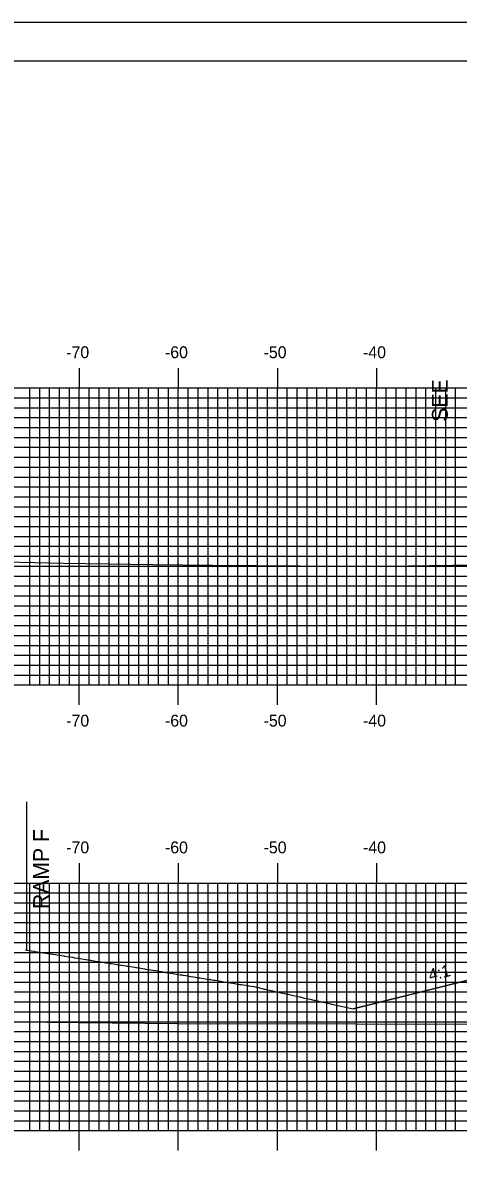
# Model space of a CAD drawing. Extents: x 854116 to 854460, y 364366 to 364586.
# Drawn here: x 854206.5 to 854250.5, y 364471.3 to 364585.7 of the extents above; entities that cross this region are included whole.
import ezdxf

# ---------------------------------------------------------------- set-up
doc = ezdxf.new("R2010")
doc.units = 0
for name, color, linetype in [('ANNOTATION', 7, 'Continuous'), ('BORDER', 7, 'Continuous'), ('D_Roadway_Centerline', 7, 'Continuous'), ('D_Roadway_SlopeLines', 7, 'Continuous'), ('D_Roadway_SubGrade', 7, 'Continuous'), ('H_V ANNOTATION', 7, 'Continuous'), ('MAJOR', 7, 'Continuous'), ('MINOR', 7, 'Continuous'), ('PLOT BOUNDARY', 7, 'Continuous'), ('S_Roadway_Centerline', 7, 'Continuous')]:
    doc.layers.add(name, color=color, linetype=linetype)

msp = doc.modelspace()

# ---------------------------------------------------------------- linework, layer by layer
at = {"layer": 'BORDER'}
msp.add_lwpolyline([(854132.63, 364371.79), (854452.63, 364371.79), (854452.63, 364581.79), (854132.63, 364581.79)], close=True, dxfattribs=at)
at = {"layer": 'D_Roadway_Centerline'}
for points in [[(854206.79, 364492.04), (854206.89, 364492.03), (854206.89, 364492.03), (854206.91, 364492.02), (854207.66, 364491.9), (854207.74, 364491.89), (854207.75, 364491.89), (854207.98, 364491.85), (854208.01, 364491.85), (854208.37, 364491.79), (854208.43, 364491.78), (854209.04, 364491.69), (854209.19, 364491.66), (854209.19, 364491.66), (854209.2, 364491.66), (854209.37, 364491.63), (854209.98, 364491.54), (854210.43, 364491.47), (854210.63, 364491.43), (854210.67, 364491.43), (854210.75, 364491.41), (854211.24, 364491.34), (854211.53, 364491.29), (854211.76, 364491.25), (854212.08, 364491.2), (854212.18, 364491.19), (854212.31, 364491.17), (854212.7, 364491.1), (854213.09, 364491.04), (854213.22, 364491.02), (854213.36, 364491), (854213.46, 364490.98), (854213.54, 364490.97), (854213.68, 364490.95), (854213.88, 364490.91), (854214.18, 364490.87), (854214.67, 364490.79), (854214.89, 364490.75), (854215, 364490.74), (854215.32, 364490.68), (854215.46, 364490.66), (854215.67, 364490.63), (854216.25, 364490.54), (854216.43, 364490.51), (854216.48, 364490.5), (854216.95, 364490.42), (854217.04, 364490.41), (854217.16, 364490.39), (854217.84, 364490.28), (854217.95, 364490.26), (854217.96, 364490.26), (854218.01, 364490.25), (854218.64, 364490.15), (854218.82, 364490.12), (854218.82, 364490.12), (854218.82, 364490.12), (854218.92, 364490.1), (854219.41, 364490.03), (854219.44, 364490.02), (854219.45, 364490.02), (854219.45, 364490.02), (854220.15, 364489.91), (854220.25, 364489.89), (854220.34, 364489.88), (854220.95, 364489.78), (854220.97, 364489.77), (854221.05, 364489.76), (854221.66, 364489.66), (854221.86, 364489.63), (854222.03, 364489.6), (854222.46, 364489.53), (854222.6, 364489.51), (854222.67, 364489.5), (854222.98, 364489.45), (854223.49, 364489.37), (854223.76, 364489.32), (854223.97, 364489.29), (854224.13, 364489.26), (854224.3, 364489.23), (854224.35, 364489.23), (854224.39, 364489.22), (854224.79, 364489.16), (854225.12, 364489.1), (854225.34, 364489.06), (854225.5, 364489.04), (854225.78, 364488.99), (854225.94, 364488.97), (854226.52, 364488.87), (854226.77, 364488.83), (854226.84, 364488.82), (854227.03, 364488.79), (854227.47, 364488.72), (854227.6, 364488.7), (854227.75, 364488.67), (854228.43, 364488.56), (854228.44, 364488.56), (854228.57, 364488.54), (854229.22, 364488.43), (854229.26, 364488.43), (854229.3, 364488.42), (854229.86, 364488.33), (854230.09, 364488.28), (854230.09, 364488.28), (854230.09, 364488.28), (854230.09, 364488.28), (854230.13, 364488.27), (854230.14, 364488.26), (854230.93, 364488.09), (854231, 364488.07), (854231.69, 364487.92), (854231.7, 364487.92), (854231.77, 364487.9), (854231.91, 364487.87), (854232.61, 364487.71), (854232.77, 364487.68), (854233.26, 364487.57), (854233.31, 364487.56), (854233.46, 364487.52), (854233.73, 364487.46), (854234.31, 364487.33), (854234.52, 364487.29), (854234.84, 364487.21), (854234.98, 364487.18), (854235.16, 364487.14), (854235.53, 364487.06), (854235.9, 364486.97), (854235.96, 364486.96), (854236.01, 364486.95), (854236.25, 364486.9), (854236.43, 364486.86), (854236.7, 364486.8), (854236.87, 364486.76), (854237.48, 364486.62), (854237.73, 364486.56), (854239.89, 364486.08)], [(854239.89, 364486.08), (854253.36, 364489.44), (854264.23, 364492.16), (854268.23, 364492.24), (854282.23, 364491.4), (854290.23, 364490.92), (854302.23, 364487.92), (854303.39, 364487.63), (854318.77, 364483.79)]]:
    msp.add_lwpolyline(points, dxfattribs=at)
at = {"layer": 'D_Roadway_SlopeLines'}
msp.add_lwpolyline([(854264.23, 364492.16), (854239.89, 364486.08)], dxfattribs=at)
at = {"layer": 'D_Roadway_SubGrade'}
msp.add_line((854206.91, 364506.98), (854206.91, 364492.02), dxfattribs=at)
at = {"layer": 'MAJOR'}
for p, q in [((854212.23, 364550.79), (854212.23, 364548.79)), ((854222.23, 364550.79), (854222.23, 364548.79)), ((854232.23, 364550.79), (854232.23, 364548.79)), ((854242.23, 364550.79), (854242.23, 364548.79)), ((854142.23, 364548.79), (854422.23, 364548.79)), ((854142.23, 364548.79), (854422.23, 364548.79)), ((854212.23, 364518.79), (854212.23, 364548.79)), ((854222.23, 364518.79), (854222.23, 364548.79)), ((854232.23, 364518.79), (854232.23, 364548.79)), ((854242.23, 364518.79), (854242.23, 364548.79)), ((854142.23, 364543.79), (854422.23, 364543.79)), ((854142.23, 364538.79), (854422.23, 364538.79)), ((854142.23, 364533.79), (854422.23, 364533.79)), ((854142.23, 364528.79), (854422.23, 364528.79)), ((854142.23, 364523.79), (854422.23, 364523.79)), ((854142.23, 364518.79), (854422.23, 364518.79)), ((854142.23, 364518.79), (854422.23, 364518.79)), ((854212.23, 364516.78), (854212.23, 364518.79)), ((854222.23, 364516.78), (854222.23, 364518.79)), ((854232.23, 364516.78), (854232.23, 364518.79)), ((854242.23, 364516.78), (854242.23, 364518.79)), ((854212.23, 364500.79), (854212.23, 364498.79)), ((854222.23, 364500.79), (854222.23, 364498.79)), ((854232.23, 364500.79), (854232.23, 364498.79)), ((854242.23, 364500.79), (854242.23, 364498.79)), ((854142.23, 364498.79), (854422.23, 364498.79)), ((854142.23, 364498.79), (854422.23, 364498.79)), ((854212.23, 364473.79), (854212.23, 364498.79)), ((854222.23, 364473.79), (854222.23, 364498.79)), ((854232.23, 364473.79), (854232.23, 364498.79)), ((854242.23, 364473.79), (854242.23, 364498.79)), ((854142.23, 364493.79), (854422.23, 364493.79)), ((854142.23, 364488.79), (854422.23, 364488.79)), ((854142.23, 364483.79), (854422.23, 364483.79)), ((854142.23, 364478.79), (854422.23, 364478.79)), ((854142.23, 364473.79), (854422.23, 364473.79)), ((854142.23, 364473.79), (854422.23, 364473.79)), ((854212.23, 364471.78), (854212.23, 364473.79)), ((854222.23, 364471.78), (854222.23, 364473.79)), ((854232.23, 364471.78), (854232.23, 364473.79)), ((854242.23, 364471.78), (854242.23, 364473.79))]:
    msp.add_line(p, q, dxfattribs=at)
at = {"layer": 'MINOR'}
for p, q in [((854207.23, 364518.79), (854207.23, 364548.79)), ((854208.23, 364518.79), (854208.23, 364548.79)), ((854209.23, 364518.79), (854209.23, 364548.79)), ((854210.23, 364518.79), (854210.23, 364548.79)), ((854211.23, 364518.79), (854211.23, 364548.79)), ((854213.23, 364518.79), (854213.23, 364548.79)), ((854214.23, 364518.79), (854214.23, 364548.79)), ((854215.23, 364518.79), (854215.23, 364548.79)), ((854216.23, 364518.79), (854216.23, 364548.79)), ((854217.23, 364518.79), (854217.23, 364548.79)), ((854218.23, 364518.79), (854218.23, 364548.79)), ((854219.23, 364518.79), (854219.23, 364548.79)), ((854220.23, 364518.79), (854220.23, 364548.79)), ((854221.23, 364518.79), (854221.23, 364548.79)), ((854223.23, 364518.79), (854223.23, 364548.79)), ((854224.23, 364518.79), (854224.23, 364548.79)), ((854225.23, 364518.79), (854225.23, 364548.79)), ((854226.23, 364518.79), (854226.23, 364548.79)), ((854227.23, 364518.79), (854227.23, 364548.79)), ((854228.23, 364518.79), (854228.23, 364548.79)), ((854229.23, 364518.79), (854229.23, 364548.79)), ((854230.23, 364518.79), (854230.23, 364548.79)), ((854231.23, 364518.79), (854231.23, 364548.79)), ((854233.23, 364518.79), (854233.23, 364548.79)), ((854234.23, 364518.79), (854234.23, 364548.79)), ((854235.23, 364518.79), (854235.23, 364548.79)), ((854236.23, 364518.79), (854236.23, 364548.79)), ((854237.23, 364518.79), (854237.23, 364548.79)), ((854238.23, 364518.79), (854238.23, 364548.79)), ((854239.23, 364518.79), (854239.23, 364548.79)), ((854240.23, 364518.79), (854240.23, 364548.79)), ((854241.23, 364518.79), (854241.23, 364548.79)), ((854243.23, 364518.79), (854243.23, 364548.79)), ((854244.23, 364518.79), (854244.23, 364548.79)), ((854245.23, 364518.79), (854245.23, 364548.79)), ((854246.23, 364518.79), (854246.23, 364548.79)), ((854247.23, 364518.79), (854247.23, 364548.79)), ((854248.23, 364518.79), (854248.23, 364548.79)), ((854249.23, 364518.79), (854249.23, 364548.79)), ((854250.23, 364518.79), (854250.23, 364548.79)), ((854142.23, 364547.79), (854422.23, 364547.79)), ((854142.23, 364546.79), (854422.23, 364546.79)), ((854142.23, 364545.79), (854422.23, 364545.79)), ((854142.23, 364544.79), (854422.23, 364544.79)), ((854142.23, 364542.79), (854422.23, 364542.79)), ((854142.23, 364541.79), (854422.23, 364541.79)), ((854142.23, 364540.79), (854422.23, 364540.79)), ((854142.23, 364539.79), (854422.23, 364539.79)), ((854142.23, 364537.79), (854422.23, 364537.79)), ((854142.23, 364536.79), (854422.23, 364536.79)), ((854142.23, 364535.79), (854422.23, 364535.79)), ((854142.23, 364534.79), (854422.23, 364534.79)), ((854142.23, 364532.79), (854422.23, 364532.79)), ((854142.23, 364531.79), (854422.23, 364531.79)), ((854142.23, 364530.79), (854422.23, 364530.79)), ((854142.23, 364529.79), (854422.23, 364529.79)), ((854142.23, 364527.79), (854422.23, 364527.79)), ((854142.23, 364526.79), (854422.23, 364526.79)), ((854142.23, 364525.79), (854422.23, 364525.79)), ((854142.23, 364524.79), (854422.23, 364524.79)), ((854142.23, 364522.79), (854422.23, 364522.79)), ((854142.23, 364521.79), (854422.23, 364521.79)), ((854142.23, 364520.79), (854422.23, 364520.79)), ((854142.23, 364519.79), (854422.23, 364519.79)), ((854207.23, 364473.79), (854207.23, 364498.79)), ((854208.23, 364473.79), (854208.23, 364498.79)), ((854209.23, 364473.79), (854209.23, 364498.79)), ((854210.23, 364473.79), (854210.23, 364498.79)), ((854211.23, 364473.79), (854211.23, 364498.79)), ((854213.23, 364473.79), (854213.23, 364498.79)), ((854214.23, 364473.79), (854214.23, 364498.79)), ((854215.23, 364473.79), (854215.23, 364498.79)), ((854216.23, 364473.79), (854216.23, 364498.79)), ((854217.23, 364473.79), (854217.23, 364498.79)), ((854218.23, 364473.79), (854218.23, 364498.79)), ((854219.23, 364473.79), (854219.23, 364498.79)), ((854220.23, 364473.79), (854220.23, 364498.79)), ((854221.23, 364473.79), (854221.23, 364498.79)), ((854223.23, 364473.79), (854223.23, 364498.79)), ((854224.23, 364473.79), (854224.23, 364498.79)), ((854225.23, 364473.79), (854225.23, 364498.79)), ((854226.23, 364473.79), (854226.23, 364498.79)), ((854227.23, 364473.79), (854227.23, 364498.79)), ((854228.23, 364473.79), (854228.23, 364498.79)), ((854229.23, 364473.79), (854229.23, 364498.79)), ((854230.23, 364473.79), (854230.23, 364498.79)), ((854231.23, 364473.79), (854231.23, 364498.79)), ((854233.23, 364473.79), (854233.23, 364498.79)), ((854234.23, 364473.79), (854234.23, 364498.79)), ((854235.23, 364473.79), (854235.23, 364498.79)), ((854236.23, 364473.79), (854236.23, 364498.79)), ((854237.23, 364473.79), (854237.23, 364498.79)), ((854238.23, 364473.79), (854238.23, 364498.79)), ((854239.23, 364473.79), (854239.23, 364498.79)), ((854240.23, 364473.79), (854240.23, 364498.79)), ((854241.23, 364473.79), (854241.23, 364498.79)), ((854243.23, 364473.79), (854243.23, 364498.79)), ((854244.23, 364473.79), (854244.23, 364498.79)), ((854245.23, 364473.79), (854245.23, 364498.79)), ((854246.23, 364473.79), (854246.23, 364498.79)), ((854247.23, 364473.79), (854247.23, 364498.79)), ((854248.23, 364473.79), (854248.23, 364498.79)), ((854249.23, 364473.79), (854249.23, 364498.79)), ((854250.23, 364473.79), (854250.23, 364498.79)), ((854142.23, 364497.79), (854422.23, 364497.79)), ((854142.23, 364496.79), (854422.23, 364496.79)), ((854142.23, 364495.79), (854422.23, 364495.79)), ((854142.23, 364494.79), (854422.23, 364494.79)), ((854142.23, 364492.79), (854422.23, 364492.79)), ((854142.23, 364491.79), (854422.23, 364491.79)), ((854142.23, 364490.79), (854422.23, 364490.79)), ((854142.23, 364489.79), (854422.23, 364489.79)), ((854142.23, 364487.79), (854422.23, 364487.79)), ((854142.23, 364486.79), (854422.23, 364486.79)), ((854142.23, 364485.79), (854422.23, 364485.79)), ((854142.23, 364484.79), (854422.23, 364484.79)), ((854142.23, 364482.79), (854422.23, 364482.79)), ((854142.23, 364481.79), (854422.23, 364481.79)), ((854142.23, 364480.79), (854422.23, 364480.79)), ((854142.23, 364479.79), (854422.23, 364479.79)), ((854142.23, 364477.79), (854422.23, 364477.79)), ((854142.23, 364476.79), (854422.23, 364476.79)), ((854142.23, 364475.79), (854422.23, 364475.79)), ((854142.23, 364474.79), (854422.23, 364474.79))]:
    msp.add_line(p, q, dxfattribs=at)
at = {"layer": 'PLOT BOUNDARY'}
msp.add_lwpolyline([(854116.44, 364365.67), (854456.44, 364365.67), (854456.44, 364585.67), (854116.44, 364585.67)], close=True, dxfattribs=at)
at = {"layer": 'S_Roadway_Centerline'}
for points in [[(854201.89, 364531.3), (854210.62, 364531.08), (854219.65, 364530.97), (854222.65, 364530.93), (854225.67, 364530.9), (854243.31, 364530.75), (854245.48, 364530.81), (854247.64, 364530.87), (854265.74, 364531.11), (854269.02, 364530.98), (854272.72, 364530.9), (854281.03, 364530.76), (854288.45, 364530.62), (854296.49, 364530.38), (854310.61, 364529.92), (854320.11, 364529.84), (854327.16, 364529.68)], [(854142.23, 364484.51), (854145.43, 364484.53), (854150.31, 364484.55), (854166.25, 364484.59), (854170.89, 364484.6), (854177.65, 364484.66), (854184.53, 364484.68), (854193.85, 364484.73), (854205.16, 364484.77), (854206.43, 364484.76), (854208.95, 364484.74), (854225.49, 364484.59), (854233.76, 364484.6), (854246.53, 364484.54), (854262.03, 364484.59), (854265.28, 364484.63), (854275.82, 364484.44), (854286.51, 364484.21), (854289.54, 364484.19), (854299.47, 364484.14), (854307.05, 364483.9), (854318.1, 364483.75), (854326.02, 364483.77)]]:
    msp.add_lwpolyline(points, dxfattribs=at)

# ---------------------------------------------------------------- texts
at = {"layer": 'ANNOTATION'}
for s, height, rotation, p in [('SEE', 1.6, 90, (854249.44, 364545.37)), ('RAMP F', 1.6, 90, (854209.17, 364496.16)), ('4:1', 1.2, 14.0362, (854247.65, 364488.88))]:
    msp.add_text(s, height=height, rotation=rotation, dxfattribs=at).set_placement(p)
at = {"layer": 'H_V ANNOTATION'}
for s, p in [('-70', (854210.91, 364551.79)), ('-60', (854220.88, 364551.79)), ('-50', (854230.84, 364551.79)), ('-40', (854240.88, 364551.79)), ('-70', (854210.91, 364514.59)), ('-60', (854220.88, 364514.59)), ('-50', (854230.84, 364514.59)), ('-40', (854240.88, 364514.59)), ('-70', (854210.91, 364501.79)), ('-60', (854220.88, 364501.79)), ('-50', (854230.84, 364501.79)), ('-40', (854240.88, 364501.79))]:
    msp.add_text(s, height=1.2, dxfattribs=at).set_placement(p)

doc.saveas('drawing.dxf')
